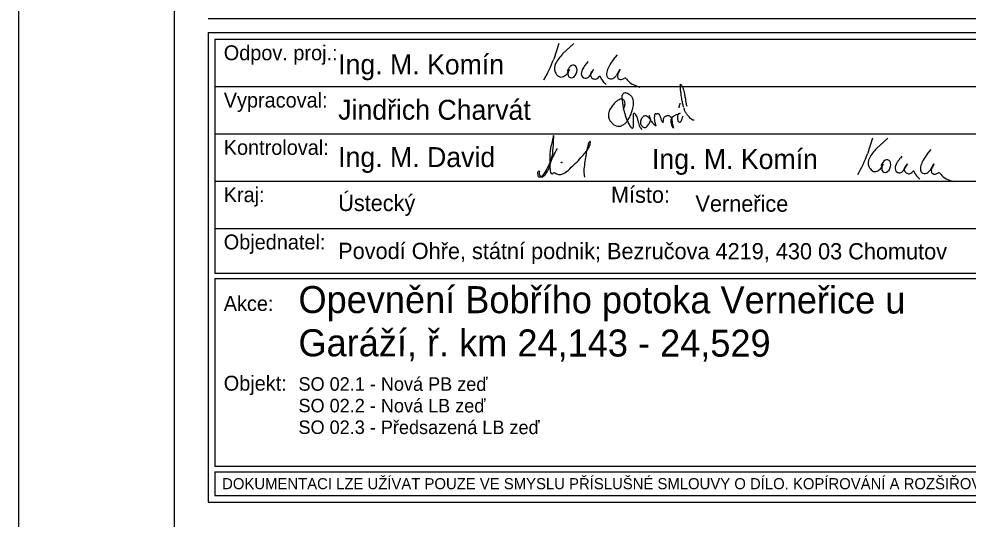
# Model space of a CAD drawing. Extents: x 67.3 to 115.4, y -93.9 to -78.3.
# Drawn here: x 92.28 to 99.3, y -86.38 to -82.68 of the extents above; entities that cross this region are included whole.
import ezdxf

# ---------------------------------------------------------------- set-up
doc = ezdxf.new("R2010")
doc.units = 0
for name, color, linetype in [('07_rozpiska', 7, 'Continuous'), ('07_rámeček', 7, 'Continuous'), ('Default', 7, 'Continuous'), ('Rozpiska + rámeček', 7, 'Continuous')]:
    doc.layers.add(name, color=color, linetype=linetype)

# ---------------------------------------------------------------- blocks, each defined once
blk = doc.blocks.new('Charvat')
at = {"layer": 'Rozpiska + rámeček'}
for points in [[(0.0826, 0.02), (0.0817, 0.0228), (0.0806, 0.0281), (0.0796, 0.0345), (0.0789, 0.0395), (0.0784, 0.0445), (0.0784, 0.0456), (0.0785, 0.0469), (0.0787, 0.0476), (0.0791, 0.0473), (0.0804, 0.0456), (0.0816, 0.0427), (0.0827, 0.0394), (0.0832, 0.0363), (0.0841, 0.0314), (0.0846, 0.0282), (0.0855, 0.0238), (0.086, 0.0216)], [(0.0108, 0.0178), (0.0123, 0.0208), (0.0129, 0.0234), (0.0122, 0.0279), (0.0108, 0.0294), (0.0087, 0.0301), (0.0059, 0.0293), (0.0024, 0.0271), (-0.0017, 0.0225), (-0.0049, 0.0177), (-0.0062, 0.0145), (-0.0067, 0.0115), (-0.0063, 0.0075), (-0.0059, 0.0064), (-0.0039, 0.0034), (-0.0014, 0.0007), (0.001, -0.001), (0.0043, -0.0019), (0.0075, -0.0019), (0.0097, -0.001), (0.0131, 0.0013), (0.0158, 0.0045), (0.0192, 0.0101), (0.022, 0.0182), (0.0223, 0.0193), (0.023, 0.0256), (0.0227, 0.0293), (0.0219, 0.0315), (0.0199, 0.034), (0.017, 0.036), (0.0147, 0.0371), (0.0142, 0.0372), (0.013, 0.0373), (0.0113, 0.0368), (0.0106, 0.0362), (0.0097, 0.0348), (0.0095, 0.0343), (0.0093, 0.0333), (0.0093, 0.0314), (0.0096, 0.0279), (0.0105, 0.0221), (0.012, 0.0151), (0.0133, 0.0108), (0.0166, 0.0023), (0.0195, -0.0026), (0.0202, -0.0035), (0.0214, -0.0042), (0.022, -0.0042), (0.0225, -0.0034), (0.023, -0.0014), (0.0231, 0), (0.0231, 0.0051), (0.0231, 0.0111), (0.0231, 0.0124), (0.0233, 0.0132), (0.0236, 0.0135), (0.024, 0.0133), (0.0254, 0.0115), (0.0268, 0.0092), (0.0279, 0.0059), (0.0289, 0.0018), (0.0298, -0.0012), (0.0315, -0.0041), (0.0327, -0.0059)], [(0.0771, 0.0198), (0.0779, 0.024), (0.0784, 0.0252)], [(0.0428, 0.0062), (0.0417, 0.0075), (0.0401, 0.009), (0.0394, 0.0095), (0.0378, 0.0101), (0.0368, 0.0101), (0.0353, 0.0098), (0.034, 0.0088), (0.0326, 0.0071), (0.0316, 0.0051), (0.0313, 0.0026), (0.0313, 0.0011), (0.0322, -0.0007), (0.0338, -0.0025), (0.0354, -0.0034), (0.0366, -0.0037), (0.0381, -0.0031), (0.0397, -0.0014), (0.0411, 0.0004), (0.0422, 0.0025), (0.043, 0.005), (0.043, 0.0063), (0.0429, 0.0069), (0.0424, 0.0086), (0.0414, 0.0106), (0.0421, 0.009), (0.0433, 0.0053), (0.0444, 0.0034), (0.0458, 0.0017), (0.0476, 0), (0.0497, -0.0015), (0.0498, -0.0016), (0.0499, -0.0016), (0.0499, -0.0014), (0.0492, 0.0003), (0.0487, 0.0022), (0.0482, 0.0055), (0.048, 0.0086), (0.0484, 0.0114), (0.0491, 0.0131), (0.0493, 0.013), (0.0506, 0.0127), (0.0522, 0.0131), (0.0539, 0.0111), (0.0547, 0.0094), (0.0552, 0.0074), (0.0556, 0.0056), (0.0566, 0.0038), (0.058, 0.0025), (0.0582, 0.0031), (0.0585, 0.0057), (0.0589, 0.0076), (0.0593, 0.0083), (0.0604, 0.0095), (0.0616, 0.0102), (0.0632, 0.0106), (0.065, 0.0106), (0.0665, 0.0094), (0.0678, 0.0078), (0.0686, 0.0033), (0.0691, 0.0001), (0.0701, -0.0031), (0.0705, -0.0044), (0.0697, -0.0035), (0.0682, -0.0005), (0.0677, 0.0025), (0.0677, 0.0059), (0.0683, 0.0079), (0.0702, 0.01), (0.0728, 0.0114), (0.0756, 0.0122), (0.0781, 0.0133), (0.0764, 0.0125), (0.0755, 0.0112), (0.0751, 0.0096), (0.0751, 0.0075), (0.0753, 0.005), (0.0753, 0.0048), (0.0758, 0.0038), (0.0766, 0.003), (0.0772, 0.0026), (0.0776, 0.0025), (0.0783, 0.0027), (0.0791, 0.0034), (0.0799, 0.0047), (0.0806, 0.0069), (0.0816, 0.0104)], [(0.0947, 0.0053), (0.0934, 0.0053), (0.0921, 0.0059), (0.0901, 0.0076), (0.0883, 0.0095), (0.0858, 0.0127), (0.0839, 0.0159), (0.0829, 0.0186), (0.0827, 0.0193)]]:
    blk.add_spline(points, degree=3, dxfattribs=at)

msp = doc.modelspace()

# ---------------------------------------------------------------- linework, layer by layer
at = {"layer": '07_rozpiska'}
msp.add_line((102.2823, -82.6813), (93.6823, -82.6813), dxfattribs=at)
for points in [[(96.2374, -83.5729), (96.2387, -83.5631), (96.2381, -83.5434), (96.2303, -83.5742), (96.2199, -83.6163), (96.2138, -83.6425), (96.2105, -83.6862), (96.2089, -83.7219), (96.2121, -83.7964), (96.2154, -83.8161), (96.228, -83.8278), (96.2325, -83.8246), (96.2335, -83.8223), (96.2406, -83.8174), (96.2533, -83.8239), (96.2669, -83.8294), (96.2818, -83.832), (96.2999, -83.8291), (96.3203, -83.8207), (96.3469, -83.7993), (96.3906, -83.7582), (96.4308, -83.717), (96.4648, -83.6785), (96.4923, -83.6451), (96.5072, -83.6121), (96.5108, -83.5959), (96.5095, -83.5891), (96.5034, -83.5904), (96.4927, -83.6137), (96.4868, -83.6376), (96.4781, -83.6794), (96.4693, -83.7351), (96.4622, -83.7912), (96.4616, -83.82), (96.4651, -83.8417), (96.4671, -83.8524)], [(96.2313, -83.6781), (96.2332, -83.6522), (96.2358, -83.6296), (96.2377, -83.6053), (96.2374, -83.5729)], [(96.1227, -83.8333), (96.1208, -83.8216), (96.1218, -83.8139), (96.1266, -83.8074), (96.1302, -83.8067), (96.1321, -83.8187), (96.1328, -83.833), (96.1409, -83.8453), (96.1522, -83.8495), (96.1629, -83.8456), (96.1723, -83.8378), (96.1775, -83.831), (96.1927, -83.8067), (96.1989, -83.7951), (96.2147, -83.7488), (96.2313, -83.6781)], [(96.2636, -83.6386), (96.2361, -83.6934), (96.1898, -83.7854), (96.1564, -83.8398), (96.1441, -83.8511), (96.1347, -83.8527), (96.1289, -83.8521), (96.1247, -83.8453), (96.1227, -83.8333)], [(96.296, -83.7403), (96.2938, -83.7413), (96.2938, -83.7433), (96.2954, -83.7442), (96.2986, -83.7449), (96.2993, -83.7433), (96.2993, -83.7416), (96.296, -83.7403)]]:
    msp.add_spline(points, degree=3, dxfattribs=at)
at = {"layer": 'Default'}
for p, q in [((96.3404, -83.0799), (96.3548, -83.054)), ((96.5824, -83.1087), (96.5924, -83.126)), ((96.614, -83.1548), (96.6256, -83.1663)), ((98.6621, -83.7799), (98.6765, -83.754)), ((98.9041, -83.8087), (98.9141, -83.826)), ((98.9357, -83.8548), (98.9473, -83.8663))]:
    msp.add_line(p, q, dxfattribs=at)
for points in [[(96.2756, -82.8639), (96.2396, -82.9791)], [(96.388, -82.8639), (96.3044, -82.9388)], [(96.7076, -82.946), (96.6788, -82.982)], [(96.4628, -83.0367), (96.46, -83.0396)], [(96.4916, -82.9964), (96.4816, -83.0108)], [(96.5276, -83.0655), (96.5348, -83.054), (96.5248, -83.0655)], [(96.7048, -83.0972), (96.7292, -83.054), (96.7192, -83.0799)], [(96.5104, -83.0972), (96.5104, -83.0972)], [(96.5132, -83.0799), (96.5132, -83.0828)], [(98.5973, -83.5639), (98.5613, -83.6791)], [(98.7097, -83.5639), (98.6261, -83.6388)], [(98.8133, -83.6964), (98.8033, -83.7108)], [(99.0293, -83.646), (99.0005, -83.682)], [(98.7845, -83.7367), (98.7817, -83.7396)], [(98.8493, -83.7655), (98.8565, -83.754), (98.8465, -83.7655)], [(99.0265, -83.7972), (99.0509, -83.754), (99.0409, -83.7799)], [(98.8321, -83.7972), (98.8321, -83.7972)], [(98.8349, -83.7799), (98.8349, -83.7828)]]:
    msp.add_lwpolyline(points, dxfattribs=at)
for centre, radius, start, end in [((95.3063, -82.6324), 0.9948, 329.80858, 339.56815), ((96.5645, -83.1806), 0.3545, 137.00062, 151.51062), ((96.9105, -83.1677), 0.2956, 141.11668, 151.43002), ((96.3168, -83.0472), 0.0732, 150.83631, 201.23374), ((96.4177, -83.0954), 0.084, 133.12102, 160.6603), ((96.3969, -83.0877), 0.0529, 142.82783, 193.29225), ((96.5486, -83.1022), 0.1085, 146.31446, 165.71836), ((96.2186, -82.8822), 0.288, 326.31446, 326.46946), ((96.7033, -83.1936), 0.288, 140.57196, 146.46893), ((96.3598, -82.9865), 0.1862, 320.58833, 335.16259), ((96.6914, -83.0884), 0.0617, 158.78845, 195.14726), ((96.8323, -83.1271), 0.2075, 150.931, 162.8917), ((96.3233, -83.0376), 0.083, 205.78195, 234.22418), ((96.2949, -83.074), 0.0369, 236.98468, 294.62862), ((96.3348, -83.1912), 0.0864, 108.04736, 108.08265), ((96.2725, -83.0298), 0.0864, 295.93387, 323.63221), ((96.4753, -83.0872), 0.0323, 245.35778, 276.92267), ((96.4682, -83.0731), 0.0475, 283.31943, 318.16716), ((96.5391, -83.0942), 0.0288, 154.94151, 187.17365), ((96.5391, -83.0955), 0.0286, 186.45097, 212.31824), ((96.5663, -83.104), 0.0576, 139.19606, 154.94016), ((96.5423, -83.0936), 0.0324, 212.08411, 258.70933), ((96.5439, -83.09), 0.0362, 257.35338, 296.27075), ((96.5376, -83.0858), 0.043, 301.37529, 327.02531), ((96.5787, -83.1121), 0.00576, 26.63136, 150.41952), ((96.6699, -83.0885), 0.0864, 206.63144, 229.82938), ((96.6572, -83.0965), 0.0265, 197.61582, 249.38851), ((96.6636, -83.0778), 0.0463, 250.12564, 275.82035), ((96.6643, -83.089), 0.035, 276.59581, 304.89281), ((96.6225, -83.0405), 0.099, 308.6573, 325.5075), ((96.7396, -83.1029), 0.0297, 172.16185, 218.17447), ((96.7766, -83.1117), 0.0677, 151.17648, 169.00349), ((96.7388, -83.0945), 0.0349, 229.93747, 256.22885), ((96.7349, -83.0829), 0.0458, 264.36538, 302.31991), ((96.7665, -83.1331), 0.0136, 38.96313, 121.674), ((96.8859, -83.0484), 0.1329, 214.99845, 231.36881), ((96.9225, -82.9828), 0.2073, 234.79421, 256.99308), ((97.628, -83.3324), 0.9948, 329.80858, 339.56815), ((98.8862, -83.8806), 0.3545, 137.00062, 151.51062), ((99.2322, -83.8677), 0.2956, 141.11668, 151.43002), ((98.6385, -83.7472), 0.0732, 150.83631, 201.23374), ((98.7394, -83.7954), 0.084, 133.12102, 160.6603), ((98.7186, -83.7877), 0.0529, 142.82783, 193.29225), ((98.8703, -83.8022), 0.1085, 146.31446, 165.71836), ((98.5403, -83.5822), 0.288, 326.31446, 326.46946), ((99.025, -83.8936), 0.288, 140.57196, 146.46893), ((98.6814, -83.6865), 0.1862, 320.58833, 335.16259), ((98.888, -83.804), 0.0576, 139.19606, 154.94016), ((99.0131, -83.7884), 0.0617, 158.78845, 195.14726), ((99.154, -83.8271), 0.2075, 150.931, 162.8917), ((98.645, -83.7376), 0.083, 205.78195, 234.22418), ((98.6166, -83.774), 0.0369, 236.98468, 294.62862), ((98.6565, -83.8912), 0.0864, 108.04736, 108.08265), ((98.5942, -83.7298), 0.0864, 295.93387, 323.63221), ((98.797, -83.7872), 0.0323, 245.35778, 276.92267), ((98.7899, -83.7731), 0.0475, 283.31943, 318.16716), ((98.8608, -83.7942), 0.0288, 154.94151, 187.17365), ((98.8608, -83.7955), 0.0286, 186.45097, 212.31824), ((98.864, -83.7936), 0.0324, 212.08411, 258.70933), ((98.8656, -83.79), 0.0362, 257.35338, 296.27075), ((98.8593, -83.7858), 0.043, 301.37529, 327.02531), ((98.9003, -83.8121), 0.00576, 26.63136, 150.41952), ((98.9916, -83.7885), 0.0864, 206.63144, 229.82938), ((98.9789, -83.7965), 0.0265, 197.61582, 249.38851), ((98.9853, -83.7778), 0.0463, 250.12564, 275.82035), ((98.986, -83.789), 0.035, 276.59581, 304.89281), ((98.9442, -83.7405), 0.099, 308.6573, 325.5075), ((99.0613, -83.8029), 0.0297, 172.16185, 218.17447), ((99.0983, -83.8117), 0.0677, 151.17648, 169.00349), ((99.0604, -83.7945), 0.0349, 229.93747, 256.22885), ((99.0566, -83.7829), 0.0458, 264.36538, 302.31991), ((99.0882, -83.8331), 0.0136, 38.96313, 121.674), ((99.2076, -83.7484), 0.1329, 214.99845, 231.36881), ((99.2442, -83.6828), 0.2073, 234.79421, 256.99308)]:
    msp.add_arc(centre, radius, start, end, dxfattribs=at)
for centre, major_axis, ratio, start_param, end_param in [((96.3764, -83.0696), (0.0152, 0.0459), 0.677007, 2.488228, 7.220838), ((96.4791, -83.0863), (-0.0357, 0.0109), 0.932374, 0, 1.363098), ((98.6981, -83.7696), (0.0152, 0.0459), 0.677007, 2.488228, 7.220838), ((98.8008, -83.7863), (-0.0357, 0.0109), 0.932374, 0, 1.363098)]:
    msp.add_ellipse(centre, major_axis=major_axis, ratio=ratio, start_param=start_param, end_param=end_param, dxfattribs=at)
at = {"layer": 'Rozpiska + rámeček'}
for p, q in [((93.6823, -82.7813), (93.6823, -86.2563)), ((93.6823, -82.7813), (102.2823, -82.7813)), ((93.7323, -82.8313), (93.7323, -84.5613)), ((93.7323, -82.8313), (99.3923, -82.8313)), ((93.7323, -83.1813), (99.3923, -83.1813)), ((93.7323, -83.5313), (99.3923, -83.5313)), ((93.7323, -83.8813), (99.3923, -83.8813)), ((93.7323, -84.2313), (99.3923, -84.2313)), ((93.7323, -84.5613), (99.3923, -84.5613)), ((93.7323, -84.6013), (99.3923, -84.6013)), ((93.7323, -84.6013), (93.7323, -85.9913)), ((93.7323, -85.9913), (99.3923, -85.9913)), ((93.7323, -86.0313), (102.2323, -86.0313)), ((93.7323, -86.0313), (93.7323, -86.2063)), ((93.7323, -86.2063), (102.2323, -86.2063)), ((93.6823, -86.2563), (102.2823, -86.2563))]:
    msp.add_line(p, q, dxfattribs=at)
for points in [[(92.2823, -79.0813), (102.7823, -79.0813), (102.7823, -93.9313), (92.2823, -93.9313)], [(93.4323, -79.0813), (102.5323, -79.0813), (102.5323, -86.5063), (93.4323, -86.5063)]]:
    msp.add_lwpolyline(points, close=True, dxfattribs=at)

# ---------------------------------------------------------------- block references
at = {"layer": '07_rámeček', "xscale": 6.250000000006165, "yscale": 6.250000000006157, "rotation": 3.739011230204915e-09}
msp.add_blockref('Charvat', (96.6853, -83.462), dxfattribs=at)

# ---------------------------------------------------------------- texts
at = {"layer": '07_rozpiska'}
for s, height, p in [('Opevnění Bobřího potoka Verneřice u ', 0.2, (94.3503, -84.8572)), ('Garáží, ř. km 24,143 - 24,529', 0.2, (94.3501, -85.1772)), ('SO 02.1 - Nová PB zeď', 0.1, (94.3504, -85.4319)), ('SO 02.2 - Nová LB zeď', 0.1, (94.3503, -85.5919)), ('SO 02.3 - Předsazená LB zeď', 0.1, (94.3502, -85.7519))]:
    msp.add_text(s, height=height, rotation=359.95393, dxfattribs=at).set_placement(p)
at = {"layer": 'Rozpiska + rámeček'}
for s, height, rotation, p in [('Odpov. proj.:', 0.11, 359.95393, (93.7973, -82.9863)), ('Ing. M. Komín', 0.147465, 359.95278, (94.644, -83.0907)), ('Vypracoval:', 0.11, 359.95393, (93.7973, -83.3363)), ('Jindřich Charvát', 0.147465, 359.95278, (94.644, -83.4263)), ('Kontroloval:', 0.11, 359.95393, (93.7973, -83.6863)), ('Ing. M. David', 0.147465, 359.95278, (94.644, -83.7763)), ('Ing. M. Komín', 0.147465, 359.95278, (96.9657, -83.7907)), ('Kraj:', 0.11, 359.95393, (93.7973, -84.0363)), ('Ústecký', 0.12, 359.95393, (94.644, -84.1023)), ('Místo:', 0.12, 359.95393, (96.6623, -84.0413)), ('Verneřice', 0.12, 359.95278, (97.2873, -84.1071)), ('Objednatel:', 0.11, 359.95393, (93.7973, -84.3863)), ('Povodí Ohře, státní podnik; Bezručova 4219, 430 03 Chomutov', 0.12, 359.95278, (94.644, -84.4571)), ('Akce:', 0.11, 359.95393, (93.7973, -84.8413)), ('Objekt:', 0.11, 359.95393, (93.7973, -85.4314))]:
    msp.add_text(s, height=height, rotation=rotation, dxfattribs=at).set_placement(p)
msp.add_text('DOKUMENTACI LZE UŽÍVAT POUZE VE SMYSLU PŘÍSLUŠNÉ SMLOUVY O DÍLO. KOPÍROVÁNÍ A ROZŠIŘOVÁNÍ POUZE PO PŘEDCHOZÍM SOUHLASU  AZ CONSULT spol. s. r.o.', height=0.0822563, dxfattribs=at).set_placement((93.7853, -86.1609))

doc.saveas('drawing.dxf')
